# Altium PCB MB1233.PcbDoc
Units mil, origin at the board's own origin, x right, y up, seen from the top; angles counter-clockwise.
Board outline 1023.62 x 1102.36 mil, 2 copper layers (Top Layer, Bottom Layer), stack 61.855 mil thick; 4 components, 10 nets, 98 pads, 48 vias.
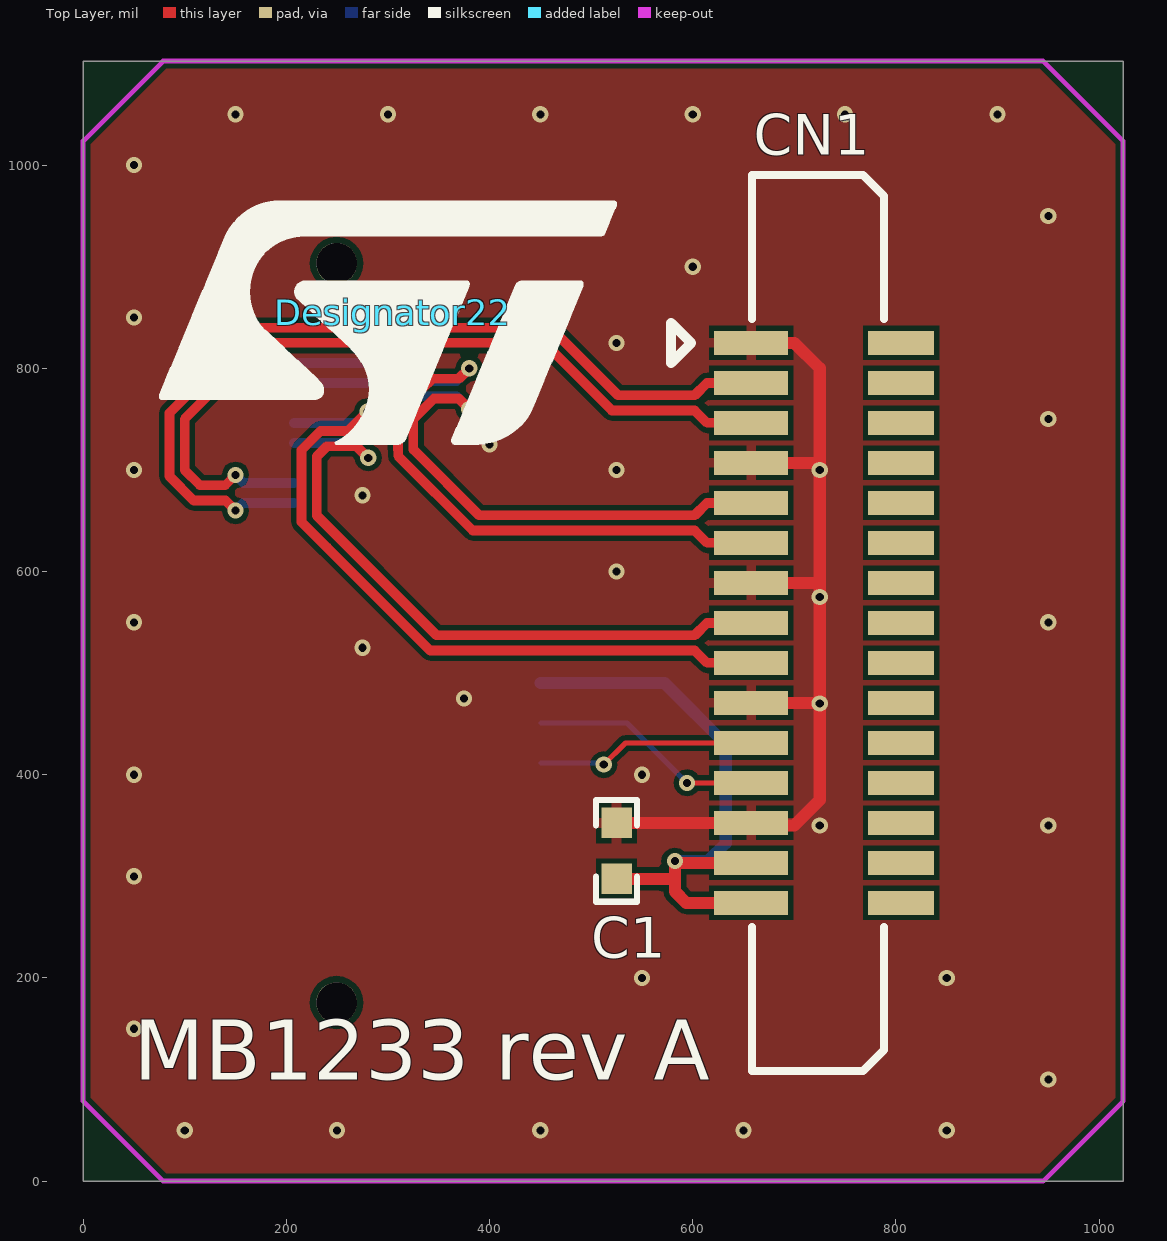
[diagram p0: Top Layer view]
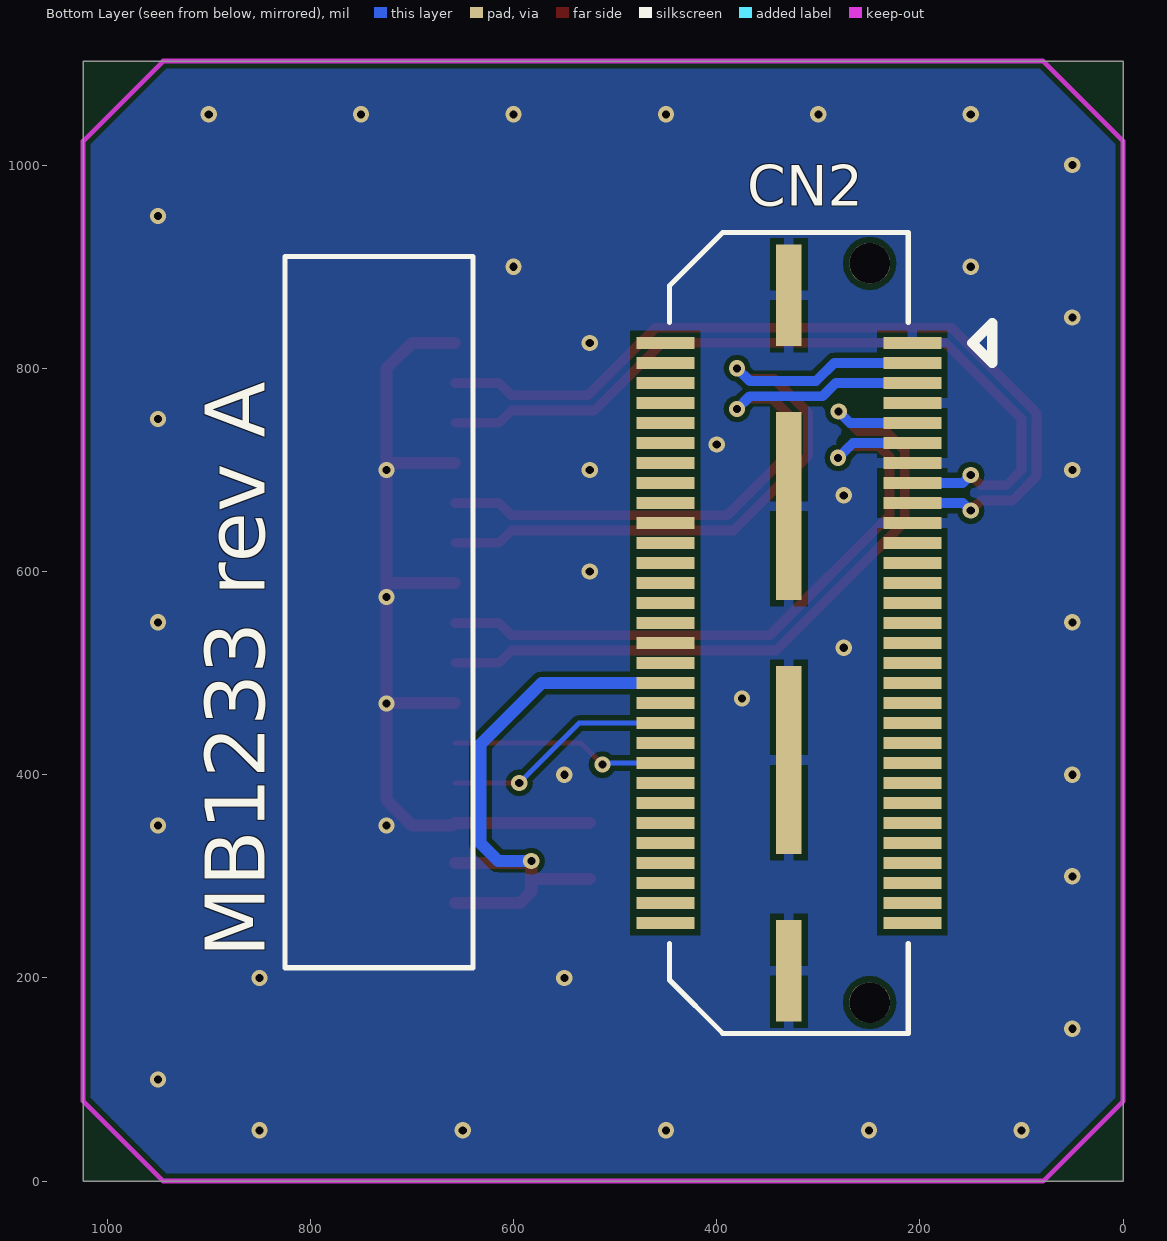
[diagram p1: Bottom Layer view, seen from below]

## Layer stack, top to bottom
Top Layer: signal copper 1.4
Dielectric: core 59.0551, FR-4, Dk 4.8
Bottom Layer: signal copper 1.4

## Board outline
0,0 0,1102.36 1023.62,1102.36 1023.62,0 0,0

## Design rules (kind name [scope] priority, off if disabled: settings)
Clearance SB [(HasFootprint('QTH-030-02-F-D-A'))] p1: gap=6
Clearance Polygon [(ObjectKind = 'Poly')] p2: gap=20
Clearance [All] p3: gap=5
DiffPairsRouting [All] p1: maxlimit=10 minlimit=5 mostfreqgap=5.3 maxuncoupledlength=500
FabricationTestPointUsage TestPointUsage [All] p1: valid=0 allowmultiple=FALSE
FabricationTestpoint Testpoint [(IsPad And (OnTopLayer Or OnBottomLayer))] p1: side=3 testpointundercomponent=TRUE minsize=40 maxsize=100 preferedsize=60 minholesize=0 maxholesize=40 preferedholesize=32 testpointgrid=1 allowsidetop=TRUE allowsidebottom=TRUE usegrid=TRUE gridtolerance=0.01
HoleSize [All] p1: absolutevalues=TRUE maxlimit=150 minlimit=1 maxpercent=80.000 minpercent=20.000
MatchedLengths "Schematic Matched Net Lengths_3" [InNet('TD_P')] p1: tolerance=100 checknetsindiffpair=TRUE checkdiffpairvsdiffpair=TRUE checkothers=TRUE
MatchedLengths "Schematic Matched Net Lengths_2" [InNet('TD_N')] p2: tolerance=100 checknetsindiffpair=TRUE checkdiffpairvsdiffpair=TRUE checkothers=TRUE
MatchedLengths "Schematic Matched Net Lengths_1" [InNet('RD_P')] p3: tolerance=100 checknetsindiffpair=TRUE checkdiffpairvsdiffpair=TRUE checkothers=TRUE
MatchedLengths "Schematic Matched Net Lengths" [InNet('RD_N')] p4: tolerance=100 checknetsindiffpair=TRUE checkdiffpairvsdiffpair=TRUE checkothers=TRUE
MinimumSolderMaskSliver [All] p1: minsoldermaskwidth=0.5
PolygonConnect VBAT [(ObjectKind = 'Poly') And (Net = 'VBAT')] p1: connectstyle=Direct reliefconductorwidth=10 reliefentries=4 polygonreliefangle="90 Angle"
PolygonConnect VDD [(ObjectKind = 'Poly') And (Net = 'VDD')] p2: connectstyle=Direct reliefconductorwidth=10 reliefentries=4 polygonreliefangle="90 Angle"
PolygonConnect VIN [(ObjectKind = 'Poly') And (Net = 'VIN')] p3: connectstyle=Direct reliefconductorwidth=10 reliefentries=4 polygonreliefangle="90 Angle"
PolygonConnect +3V3 [(ObjectKind = 'Poly') And (Net = '+3V3')] p4: connectstyle=Direct reliefconductorwidth=10 reliefentries=4 polygonreliefangle="90 Angle"
PolygonConnect E5V [(ObjectKind = 'Poly') And (Net = 'E5V')] p5: connectstyle=Direct reliefconductorwidth=10 reliefentries=4 polygonreliefangle="90 Angle"
PolygonConnect +5V [(ObjectKind = 'Poly') And (Net = '+5V')] p6: connectstyle=Direct reliefconductorwidth=10 reliefentries=4 polygonreliefangle="90 Angle"
PolygonConnect U5V [(ObjectKind = 'Poly') And (Net = 'NetC17_2')] p7: connectstyle=Direct reliefconductorwidth=10 reliefentries=4 polygonreliefangle="90 Angle"
PolygonConnect VIA [IsVia] p8: connectstyle=Direct reliefconductorwidth=20 reliefentries=4 polygonreliefangle="90 Angle"
PolygonConnect [All] p9: connectstyle=Relief reliefconductorwidth=10 reliefentries=4 polygonreliefangle="90 Angle"
RoutingLayers [All] p1: top layer_v5=FALSE bottom layer_v5=FALSE
RoutingVias [All] p1: holewidth=12 width=20 viastyle="Through Hole" minholewidth=8 minwidth=15 maxholewidth=28 maxwidth=50
SilkToSilkClearance [All] p1: silktosilkclearance=4
SilkscreenOverComponentPads [IsPad] p1: minsilkscreentomaskgap=4
SolderMaskExpansion [All] p1: expansion=4
Width PWR [InNetClass('PWR')] p1: maxlimit=100 minlimit=8 preferedwidth=12 minimp=50.000000 maximp=50.000000 favimp=50.000000
Width [All] p2: maxlimit=100 minlimit=5 preferedwidth=5 minimp=50.000000 maximp=50.000000 favimp=50.000000
20 further rules are at their usual default settings.

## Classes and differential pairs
differential pair NewDifferentialPair1: +DSI_CK_N -DSI_CK_P
differential pair NewDifferentialPair2: +DSI_D0_N -DSI_D0_P
differential pair NewDifferentialPair3: +DSI_D0_N -DSI_D0_P
differential pair NewDifferentialPair4: +DSI_D1_N -DSI_D1_P

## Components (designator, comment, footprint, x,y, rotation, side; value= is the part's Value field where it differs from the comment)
C1 "100nF" 0603C 525,325 r90 top
CN1 "1-1734248-5" 1-1734248-5-SMT 657.48,825 r90 top
CN2 "QTH-030-02-F-D-A" QTH-030-02-F-D-A 207.48,825 r270 bottom
Designator22 "Comment" ST_LOGO_10mm 305,855 r0 top

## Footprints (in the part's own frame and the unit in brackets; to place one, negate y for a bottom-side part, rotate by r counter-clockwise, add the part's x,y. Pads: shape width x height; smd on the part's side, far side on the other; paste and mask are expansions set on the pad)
1-1734248-5-SMT [mm]
  rect 0.6x1.85 smd: 1(0,0) 2(-1,0) 3(-2,0) 4(-3,0) 5(-4,0) 6(-5,0) 7(-6,0) 8(-7,0) 9(-8,0) 10(-9,0) 11(-10,0) 12(-11,0) 13(-12,0) 14(-13,0) 15(-14,0)
  rect 0.6x1.65 smd: 16(0,-3.75) 17(-1,-3.75) 18(-2,-3.75) 19(-3,-3.75) 20(-4,-3.75) 21(-5,-3.75) 22(-6,-3.75) 23(-7,-3.75) 24(-8,-3.75) 25(-9,-3.75) 26(-10,-3.75) 27(-11,-3.75) 28(-12,-3.75) 29(-13,-3.75) 30(-14,-3.75)
  silkscreen extent -18.2,-3.32 4.2,2
0603C [mil]
  rect 30x30 smd: 1(27.5,0) 2(-27.5,0)
  silkscreen extent -50,-20 50,20
QTH-030-02-F-D-A [mil]
  round 40 hole 40: 0(-78.3,-42) 0(649.3,-42)
  rect 12x57 smd: 1(0,0) 2(0,-243) 3(19.69,0) 4(19.69,-243) 5(39.37,0) 6(39.37,-243) 7(59.06,0) 8(59.06,-243) 9(78.74,0) 10(78.74,-243) 11(98.43,0) 12(98.43,-243) 13(118.11,0) 14(118.11,-243) 15(137.8,0) 16(137.8,-243) 17(157.48,0) 18(157.48,-243) 19(177.17,0) 20(177.17,-243) 21(196.85,0) 22(196.85,-243) 23(216.54,0) 24(216.54,-243) 25(236.22,0) 26(236.22,-243) 27(255.91,0) 28(255.91,-243) 29(275.59,0) 30(275.59,-243) 31(295.28,0) 32(295.28,-243) 33(314.96,0) 34(314.96,-243) 35(334.65,0) 36(334.65,-243) 37(354.33,0) 38(354.33,-243) 39(374.02,0) 40(374.02,-243) 41(393.7,0) 42(393.7,-243) 43(413.39,0) 44(413.39,-243) 45(433.07,0) 46(433.07,-243) 47(452.76,0) 48(452.76,-243) 49(472.44,0) 50(472.44,-243) 51(492.13,0) 52(492.13,-243) 53(511.81,0) 54(511.81,-243) 55(531.5,0) 56(531.5,-243) 57(551.18,0) 58(551.18,-243) 59(570.87,0) 60(570.87,-243)
  rect 100x25 smd: 61(618,-121.5) 64(-47,-121.5)
  rect 185x25 smd: 62(410.5,-121.5) 63(160.6,-121.5)
  silkscreen extent -109,-239 680,79
ST_LOGO_10mm [mil]
  silkscreen extent -230,-130 220,110

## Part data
C1: library part CAP, "Capacitor"
CN1: library part "Header 15X2A", "Header, 15-Pin, Dual row"
CN2: "HIGH SPEED TERMINAL STRIP, .5mm PITCH, 60 PINS."

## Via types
v1: diameter 16, hole 8, Top Layer to Bottom Layer, tented both sides, 48 vias

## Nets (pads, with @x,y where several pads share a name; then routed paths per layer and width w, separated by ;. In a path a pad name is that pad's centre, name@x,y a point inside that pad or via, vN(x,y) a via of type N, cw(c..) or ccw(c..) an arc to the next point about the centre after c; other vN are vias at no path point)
DSI_CK_N: CN1.5 CN2.5 | length 645.1
  Top Layer w9.7: v1(380,760) 369.7,770.3 345.3,770.3 325,750 325,720 389.67,655.33 602.03,655.33 614.21,667.52 CN1.5
  Bottom Layer w9.7: CN2.5 282.79,785.63 295.92,772.5 322.8,772.5 367.5,772.5 v1(380,760)
DSI_CK_P: CN1.6 CN2.3 | length 698.5
  Top Layer w9.5: 310.1,720 310.1,713.83 383.49,640.43 601.93,640.43 614.21,628.15 CN1.6
  Top Layer w9.7: 310,720 310,756.21 339.09,785.3 339.19,785.3 343.59,789.7 369.7,789.7 v1(380,800)
  Bottom Layer w9.7: CN2.3 284.32,805.31 302.13,787.5 367.5,787.5 v1(380,800)
DSI_D0_N: CN1.8 CN2.11 | length 678.3
  Top Layer w9.7: v1(280.61,711.87) 269.16,723.32 240,723.32 230,713.32 230,655 347.78,537.22 602.03,537.22 614.21,549.41 CN1.8
  Bottom Layer w9.7: CN2.11 265.91,726.57 v1(280.61,711.87)
DSI_D0_P: CN1.9 CN2.9 | length 728.6
  Top Layer w9.5: 240.07,623.86 341.6,522.32 601.93,522.32 614.21,510.04 CN1.9
  Top Layer w9.7: 240,623.79 215,648.79 215,719.58 233.76,738.34 260.82,738.34 v1(280,757.52)
  Bottom Layer w9.7: CN2.9 268.74,746.26 v1(280,757.52)
DSI_D1_N: CN1.2 CN2.17 | length 841.5
  Top Layer w9.7: v1(150,660) 140,670 108.83,670 85.1,693.73 85.1,756.17 89.46,760.54 168.83,839.9 460.1,839.9 526.56,773.44 602.03,773.44 614.21,785.63 CN1.2
  Bottom Layer w9.7: v1(150,660) 157.52,667.52 CN2.17
DSI_D1_P: CN1.3 CN2.15 | length 792.4
  Top Layer w9.5: v1(150,695) 139.9,684.9 115,684.9 100,699.9 100,750 175,825 453.93,825 520.38,758.54 601.93,758.54 614.21,746.26 CN1.3
  Bottom Layer w9.7: v1(150,695) 157.8,687.2 CN2.15
GND: C1.1 CN1.1 CN1.4 CN1.7 CN1.10 CN1.13 CN2.1 CN2.7 CN2.13 CN2.19 CN2.61 CN2.62 CN2.63 CN2.64 | length 918.4
  Top Layer w12: C1.1 525.06,352.56 CN1.13 660.04,350 700,350 725,375 v1(725,470) ; CN1.10 724.33,470.67 v1(725,470) ; CN1.7 723.78,588.78 725,590 ; CN1.4 723.11,706.89 v1@725,705 ; CN1.1 700,825 725,800 v1@725,705 ; v1(725,470) v1(725,575) 725,590 ; 725,590 v1(725,700) v1@725,705
  other v1: 100,50 250,50 450,50 650,50 850,50 950,100 50,150 550,200 850,200 50,300 725,350 950,350 50,400 550,400 375,475 275,525 50,550 950,550 525,600 275,675 50,700 525,700 400,725 950,750 525,825 50,850 150,900 600,900 950,950 50,1000 150,1050 300,1050 450,1050 600,1050 750,1050 900,1050
I2C_SCL: CN1.11 CN2.44 | length 216.5
  Top Layer w5: v1(512.48,410) 533.78,431.3 CN1.11
  Bottom Layer w5: CN2.44 510.87,411.61 v1(512.48,410)
I2C_SDA: CN1.12 CN2.40 | length 231.5
  Top Layer w5: v1(594.41,391.93) CN1.12
  Bottom Layer w5: CN2.40 535.35,450.98 v1(594.41,391.93)
VDD: C1.2 CN1.14 CN1.15 CN2.36 | length 605.7
  Top Layer w12: C1.2 579.98,297.5 582.48,300 ; CN1.15 593.66,273.82 582.48,285 582.48,300 ; CN1.14 584.29,313.19 v1(582.48,315) 582.48,300
  Bottom Layer w12: CN2.36 572.13,490.35 632.48,430 632.48,332.48 615,315 v1(582.48,315)
pads on no net: CN1.16 CN1.17 CN1.18 CN1.19 CN1.20 CN1.21 CN1.22 CN1.23 CN1.24 CN1.25 CN1.26 CN1.27 CN1.28 CN1.29 CN1.30 CN2.0 CN2.2 CN2.4 CN2.6 CN2.8 CN2.10 CN2.12 CN2.14 CN2.16 CN2.18 CN2.20 CN2.21 CN2.22 CN2.23 CN2.24 CN2.25 CN2.26 CN2.27 CN2.28 CN2.29 CN2.30 CN2.31 CN2.32 CN2.33 CN2.34 CN2.35 CN2.37 CN2.38 CN2.39 CN2.41 CN2.42 CN2.43 CN2.45 CN2.46 CN2.47 CN2.48 CN2.49 CN2.50 CN2.51 CN2.52 CN2.53 CN2.54 CN2.55 CN2.56 CN2.57 CN2.58 CN2.59 CN2.60

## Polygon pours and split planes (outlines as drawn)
GND on Top Layer "Top Layer-No Net 1" (solid, remove dead copper, pour order 2): 0,1105 0,0 1025,0 1025,1105 5,1105
GND on Bottom Layer "Top Layer-No Net 1" (solid, remove dead copper, pour order 4): 0,1105 0,0 1025,0 1025,1105 5,1105 0,1105

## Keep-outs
Keep-Out Layer:
  lines w5: 0,78.74 0,1023.62 78.74,1102.36 944.88,1102.36 1023.62,1023.62 1023.62,78.74 944.88,0 78.74,0 0,78.74

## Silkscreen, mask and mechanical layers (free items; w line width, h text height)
Top Overlay:
  text "MB1233 rev A" at 50,100 h59.06
Bottom Overlay:
  lines w5: 640,210 640,910 825,910 825,210 640,210
  text "MB1233 rev A" at 845,220 h59.06 r270
Mechanical 1:
  lines w1: 1360,550.5 1765,550.5 ; 1360,563.8 1765,563.8 ; 1300,454 ccw(c1304,454) 1304,450 1821,450 ccw(c1821,454) 1825,454 1825,596 ccw(c1821,596) 1821,600 1304,600 ccw(c1304,596) 1300,596 1300,454
  lines w5: 0,78.74 78.74,0 944.88,0 1023.62,78.74 1023.62,1023.62 944.88,1102.36 78.74,1102.36 0,1023.62 0,78.74
  text "MB1233" at 75,1275 h60
  text "Layer Stack Up Detail for: MB1233.PcbDoc" at 1360,574.4 h10
  text "Layer" at 1360,558.8 h3
  text "Gerber" at 1445.48,558.8 h3
  text "Copper" at 1494.57,558.8 h3
  text "Dielectric" at 1548.56,558.8 h3
  text "Dielectric" at 1604.64,558.8 h3
  text "Dielectric" at 1670.13,558.8 h3
  text "Dielectric" at 1726.22,558.8 h3
  text "Name" at 1360,552.8 h3
  text "Document" at 1445.48,552.8 h3
  text "Thickness" at 1494.57,552.8 h3
  text "Height" at 1548.56,552.8 h3
  text "Material" at 1604.64,552.8 h3
  text "Constant" at 1670.13,552.8 h3
  text "Type" at 1726.22,552.8 h3
  text "Top Solder Mask" at 1360,540.62 h4
  text "(.GTS)" at 1445.48,540.62 h4
  text "0.4mil" at 1548.56,540.62 h4
  text "Solder Resist" at 1604.64,540.62 h4
  text "3.50" at 1670.13,540.62 h4
  text "Top Layer" at 1360,521.88 h4
  text "(.GTL)" at 1445.48,521.88 h4
  text "1.4mil" at 1494.57,521.88 h4
  text "59.055mil" at 1548.56,512.5 h4
  text "FR-4" at 1604.64,512.5 h4
  text "4.80" at 1670.13,512.5 h4
  text "Core" at 1726.22,512.5 h4
  text "Bottom Layer" at 1360,503.12 h4
  text "(.GBL)" at 1445.48,503.12 h4
  text "1.4mil" at 1494.57,503.12 h4
  text "Bottom Solder Mask" at 1360,484.38 h4
  text "(.GBS)" at 1445.48,484.38 h4
  text "0.4mil" at 1548.56,484.38 h4
  text "Solder Resist" at 1604.64,484.38 h4
  text "3.50" at 1670.13,484.38 h4
Drill Drawing:
  lines w5: 1459,1856 1479,1856
  lines w10: 1204,1556 3599,1556 ; 1204,1656 3200,1656 3600,1656 3600,1657 ; 1204,1756 3200,1756 3600,1756 3600,1757 ; 1684,1458 1684,1856 ; 2004,1458 2004,1856 ; 2404,1458 2404,1856 ; 3200,1458 3600,1458 3600,1856 3200,1856 ; 3200,1458 3200,1856 ; 3200,1458 1204,1458 1204,1856 3200,1856
  text "IMPEDANCE TABLE" at 1210,1918 h49.21
  text "LAYER" at 1283,1781 h49.21
  text "WIDTH" at 1741,1781 h49.21
  text "Clearance" at 2063,1781 h49.21
  text "TOLERANCE" at 3209,1780 h49.21
  text "Differential Impedence" at 2457,1778.66 h49.21
  text "Layer1,2" at 1283,1692 h49.21
  text "9.7mil" at 1730,1679 h49.21
  text "5.3mil" at 2110,1677 h49.21
  text "100 OHM" at 2602,1677 h49.21
  text "+/- 10%" at 3244,1677 h49.21
  text ".legend" at 1300,1000 h40

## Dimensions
78.74,1102.36 to 78.74,0 on Drill Drawing
0,1023.62 to 1023.62,1023.62 on Drill Drawing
